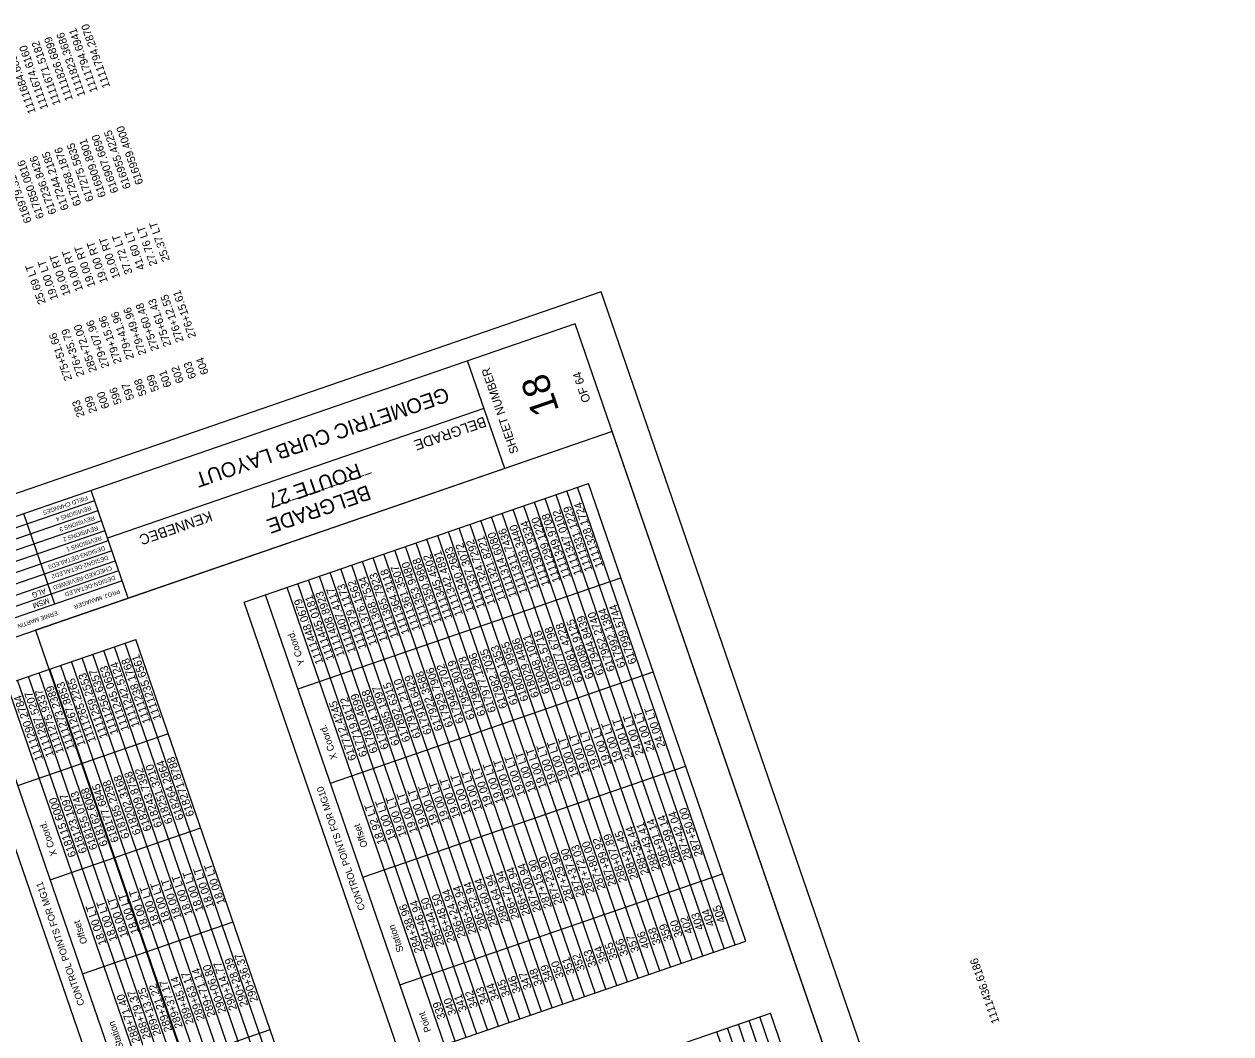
# Model space of a CAD drawing. Extents: x 1111039 to 1111836, y 617707 to 618808.
# Drawn here: x 1111305 to 1111836, y 618364 to 618808 of the extents above; entities that cross this region are included whole.
import ezdxf

# ---------------------------------------------------------------- set-up
doc = ezdxf.new("R2010")
doc.units = 0
for name, color, linetype in [('ANNOTATION', 7, 'Continuous'), ('BORDER', 7, 'Continuous'), ('BRIDGE_TITLE', 7, 'Continuous'), ('CLIPS', 7, 'Continuous'), ('H_V CONTROLS', 7, 'Continuous'), ('HIGHWAY_TITLE', 7, 'Continuous'), ('PLOT BOUNDARY', 7, 'Continuous')]:
    doc.layers.add(name, color=color, linetype=linetype)

msp = doc.modelspace()

# ---------------------------------------------------------------- linework, layer by layer
at = {"layer": 'BORDER'}
for p, q in [((1111547.51, 618675.96), (1111051.11, 618505.04)), ((1111807.98, 617919.56), (1111547.52, 618675.97)), ((1111516.51, 618612.41), (1111500.23, 618659.69)), ((1111507.41, 618638.84), (1111341.94, 618581.87)), ((1111563.79, 618628.69), (1111067.39, 618457.77)), ((1111351.05, 618555.44), (1111334.77, 618602.71))]:
    msp.add_line(p, q, dxfattribs=at)
for points in [[(1111336.27, 618598.31), (1111253.55, 618569.82)], [(1111337.78, 618593.9), (1111255.07, 618565.42)], [(1111339.3, 618589.5), (1111256.58, 618561.02)], [(1111318.87, 618552.9), (1111305.22, 618592.54)], [(1111340.82, 618585.09), (1111258.1, 618556.61)], [(1111342.33, 618580.69), (1111259.62, 618552.21)], [(1111343.85, 618576.28), (1111261.13, 618547.8)], [(1111262.65, 618543.4), (1111345.37, 618571.88)], [(1111346.88, 618567.47), (1111264.17, 618538.99)], [(1111348.4, 618563.07), (1111269.02, 618535.74)]]:
    msp.add_lwpolyline(points, dxfattribs=at)
at = {"layer": 'CLIPS'}
msp.add_lwpolyline([(1111807.98, 617919.56), (1111563.8, 618628.7), (1111310.4, 618541.44), (1111554.58, 617832.3)], close=True, dxfattribs=at)
at = {"layer": 'H_V CONTROLS'}
for p, q in [((1111402, 618553.73), (1111553.28, 618605.82)), ((1111617.74, 618403.27), (1111548.56, 618604.19)), ((1111622.47, 618404.89), (1111553.28, 618605.82)), ((1111603.56, 618398.38), (1111534.37, 618599.3)), ((1111608.28, 618400.01), (1111539.1, 618600.93)), ((1111613.01, 618401.64), (1111543.83, 618602.56)), ((1111589.37, 618393.5), (1111520.19, 618594.42)), ((1111594.1, 618395.13), (1111524.92, 618596.05)), ((1111598.83, 618396.75), (1111529.65, 618597.68)), ((1111575.19, 618388.61), (1111506.01, 618589.54)), ((1111579.92, 618390.24), (1111510.74, 618591.17)), ((1111584.65, 618391.87), (1111515.46, 618592.79)), ((1111556.28, 618382.1), (1111487.1, 618583.03)), ((1111561.01, 618383.73), (1111491.83, 618584.65)), ((1111565.74, 618385.36), (1111496.55, 618586.28)), ((1111570.46, 618386.99), (1111501.28, 618587.91)), ((1111542.1, 618377.22), (1111472.92, 618578.14)), ((1111546.83, 618378.85), (1111477.64, 618579.77)), ((1111551.55, 618380.48), (1111482.37, 618581.4)), ((1111527.92, 618372.34), (1111458.73, 618573.26)), ((1111532.64, 618373.96), (1111463.46, 618574.89)), ((1111537.37, 618375.59), (1111468.19, 618576.51)), ((1111513.73, 618367.45), (1111444.55, 618568.38)), ((1111518.46, 618369.08), (1111449.28, 618570)), ((1111523.19, 618370.71), (1111454, 618571.63)), ((1111494.82, 618360.94), (1111425.64, 618561.86)), ((1111425.7, 618515.61), (1111567.53, 618564.45)), ((1111499.55, 618362.57), (1111430.37, 618563.49)), ((1111504.28, 618364.2), (1111435.09, 618565.12)), ((1111509.01, 618365.83), (1111439.82, 618566.75)), ((1111480.64, 618356.06), (1111411.46, 618556.98)), ((1111490.09, 618359.31), (1111420.91, 618560.24)), ((1111471.18, 618352.8), (1111402, 618553.73)), ((1111278.86, 618511.33), (1111354.5, 618537.37)), ((1111418.96, 618334.82), (1111349.78, 618535.74)), ((1111423.69, 618336.45), (1111354.5, 618537.37)), ((1111423.69, 618336.45), (1111354.5, 618537.37)), ((1111404.78, 618329.94), (1111335.59, 618530.86)), ((1111409.51, 618331.56), (1111340.32, 618532.49)), ((1111414.23, 618333.19), (1111345.05, 618534.12)), ((1111390.59, 618325.05), (1111321.41, 618525.98)), ((1111395.32, 618326.68), (1111326.14, 618527.6)), ((1111400.05, 618328.31), (1111330.87, 618529.23)), ((1111371.68, 618318.54), (1111302.5, 618519.46)), ((1111376.41, 618320.17), (1111307.23, 618521.09)), ((1111381.14, 618321.8), (1111311.96, 618522.72)), ((1111385.87, 618323.43), (1111316.68, 618524.35)), ((1111439.94, 618474.25), (1111581.77, 618523.08)), ((1111357.5, 618313.66), (1111288.32, 618514.58)), ((1111366.96, 618316.91), (1111297.77, 618517.84)), ((1111348.05, 618310.4), (1111278.86, 618511.33)), ((1111302.56, 618473.21), (1111368.75, 618496)), ((1111454.19, 618432.88), (1111596.02, 618481.72)), ((1111316.81, 618431.85), (1111382.99, 618454.64)), ((1111470.47, 618385.61), (1111612.29, 618434.44)), ((1111331.05, 618390.48), (1111397.24, 618413.27)), ((1111471.18, 618352.8), (1111622.47, 618404.89)), ((1111557.73, 618347.19), (1111633.37, 618373.23)), ((1111697.82, 618170.68), (1111628.64, 618371.61)), ((1111702.55, 618172.31), (1111633.37, 618373.23)), ((1111702.55, 618172.31), (1111633.37, 618373.23)), ((1111347.33, 618343.21), (1111413.51, 618366)), ((1111683.64, 618165.8), (1111614.46, 618366.72)), ((1111688.37, 618167.43), (1111619.19, 618368.35)), ((1111693.1, 618169.06), (1111623.91, 618369.98)), ((1111678.91, 618164.17), (1111609.73, 618365.09))]:
    msp.add_line(p, q, dxfattribs=at)
at = {"layer": 'PLOT BOUNDARY'}
msp.add_lwpolyline([(1111835.61, 617886.27), (1111558.88, 618689.96), (1111038.85, 618510.9), (1111315.58, 617707.21)], close=True, dxfattribs=at)

# ---------------------------------------------------------------- texts
at = {"layer": 'ANNOTATION'}
for s, height, p in [('1111794.6941', 3.45, (1111337.74, 618778.28)), ('1111794.2870', 3.45, (1111343.19, 618780.16)), ('1111826.6899', 3.45, (1111326.85, 618774.53)), ('1111823.3686', 3.45, (1111332.29, 618776.4)), ('1111684.6898', 3.45, (1111310.5, 618768.9)), ('1111674.6160', 3.45, (1111315.95, 618770.78)), ('1111671.5182', 3.45, (1111321.4, 618772.65)), ('616907.6690', 3.45, (1111346.88, 618734.04)), ('616955.4225', 3.45, (1111352.33, 618735.91)), ('616959.4000', 3.45, (1111357.78, 618737.79)), ('617268.1876', 3.45, (1111330.54, 618728.41)), ('617275.5635', 3.45, (1111335.99, 618730.28)), ('616909.8901', 3.45, (1111341.43, 618732.16)), ('617850.0816', 3.45, (1111314.2, 618722.78)), ('617236.8426', 3.45, (1111319.64, 618724.66)), ('617244.2185', 3.45, (1111325.09, 618726.53)), ('616979.3193', 3.45, (1111308.75, 618720.9)), ('41.60 LT', 3.45, (1111358.53, 618700.22)), ('27.76 LT', 3.45, (1111363.97, 618702.1)), ('25.37 LT', 3.45, (1111369.42, 618703.97)), ('19.00 RT', 3.45, (1111342.18, 618694.6)), ('19.00 RT', 3.45, (1111347.63, 618696.47)), ('37.72 LT', 3.45, (1111353.08, 618698.35)), ('19.00 RT', 3.45, (1111325.84, 618688.97)), ('19.00 RT', 3.45, (1111331.29, 618690.84)), ('19.00 RT', 3.45, (1111336.73, 618692.72)), ('25.69 LT', 3.45, (1111314.94, 618685.22)), ('19.00 LT', 3.45, (1111320.39, 618687.09)), ('276+15.61', 3.45, (1111380.99, 618670.37)), ('275+60.48', 3.45, (1111364.65, 618664.74)), ('275+61.43', 3.45, (1111370.1, 618666.62)), ('276+12.55', 3.45, (1111375.54, 618668.5)), ('279+15.96', 3.45, (1111348.31, 618659.12)), ('279+41.96', 3.45, (1111353.75, 618660.99)), ('279+49.96', 3.45, (1111359.2, 618662.87)), ('276+35.79', 3.45, (1111331.96, 618653.49)), ('285+72.00', 3.45, (1111337.41, 618655.36)), ('279+07.96', 3.45, (1111342.86, 618657.24)), ('275+51.66', 3.45, (1111326.51, 618651.61)), ('602', 3.45, (1111375.62, 618650.58)), ('603', 3.45, (1111381.07, 618652.46)), ('604', 3.45, (1111386.51, 618654.33)), ('599', 3.45, (1111364.72, 618646.83)), ('601', 3.45, (1111370.17, 618648.71)), ('596', 3.45, (1111348.38, 618641.2)), ('597', 3.45, (1111353.83, 618643.08)), ('598', 3.45, (1111359.28, 618644.95)), ('283', 3.45, (1111332.04, 618635.58)), ('299', 3.45, (1111337.48, 618637.45)), ('600', 3.45, (1111342.93, 618639.33)), ('1111347.0102', 3.5156, (1111550.47, 618566.28)), ('1111331.1229', 3.5156, (1111555.15, 618567.9)), ('1111328.1724', 3.5156, (1111559.91, 618569.53)), ('1111301.9334', 3.5156, (1111536.35, 618561.42)), ('1111299.1220', 3.5156, (1111541.11, 618563.06)), ('1111349.9708', 3.5156, (1111545.68, 618564.63)), ('1111321.8221', 3.5156, (1111517.2, 618554.83)), ('1111314.6080', 3.5156, (1111521.95, 618556.46)), ('1111311.7436', 3.5156, (1111526.65, 618558.08)), ('1111303.3440', 3.5156, (1111531.5, 618559.75)), ('1111340.2683', 3.5156, (1111503.15, 618549.99)), ('1111337.3072', 3.5156, (1111507.87, 618551.62)), ('1111324.7292', 3.5156, (1111512.48, 618553.2)), ('1111350.9868', 3.5156, (1111488.92, 618545.09)), ('1111345.4502', 3.5156, (1111493.64, 618546.71)), ('1111342.4891', 3.5156, (1111498.21, 618548.29)), ('1111364.3118', 3.5156, (1111474.76, 618540.22)), ('1111361.3507', 3.5156, (1111479.41, 618541.81)), ('1111353.9480', 3.5156, (1111484.12, 618543.44)), ('1111379.1173', 3.5156, (1111455.83, 618533.7)), ('1111376.1562', 3.5156, (1111460.53, 618535.31)), ('1111368.7534', 3.5156, (1111465.25, 618536.94)), ('1111365.7923', 3.5156, (1111469.97, 618538.56)), ('1111445.0181', 3.5156, (1111441.65, 618528.81)), ('1111408.8923', 3.5156, (1111446.28, 618530.41)), ('1111407.4117', 3.5156, (1111451.11, 618532.07)), ('1111448.0679', 3.5156, (1111436.86, 618527.16)), ('617999.5744', 3.5156, (1111574.51, 618527.15)), ('618088.9125', 3.5156, (1111555.71, 618520.67)), ('617944.8439', 3.5156, (1111560.27, 618522.24)), ('617952.2740', 3.5156, (1111565.07, 618523.9)), ('617992.1384', 3.5156, (1111569.75, 618525.51)), ('618055.5718', 3.5156, (1111541.25, 618515.69)), ('618077.6798', 3.5156, (1111546.1, 618517.36)), ('618081.4228', 3.5156, (1111550.95, 618519.03)), ('618021.9955', 3.5156, (1111527.07, 618510.81)), ('618029.4486', 3.5156, (1111531.79, 618512.44)), ('618048.1021', 3.5156, (1111536.55, 618514.07)), ('1111235.6561', 3.5156, (1111365.59, 618502.63)), ('617977.1296', 3.5156, (1111512.8, 618505.9)), ('617982.7035', 3.5156, (1111517.75, 618507.6)), ('617990.1353', 3.5156, (1111522.47, 618509.23)), ('1111245.0653', 3.5156, (1111351.55, 618497.79)), ('1111242.5124', 3.5156, (1111356.19, 618499.39)), ('1111238.1768', 3.5156, (1111361.02, 618501.05)), ('617929.7906', 3.5156, (1111494, 618499.43)), ('617948.3702', 3.5156, (1111498.72, 618501.05)), ('617955.8019', 3.5156, (1111503.51, 618502.7)), ('617969.6978', 3.5156, (1111508.23, 618504.33)), ('1111265.2265', 3.45, (1111337, 618492.78)), ('1111259.2553', 3.5156, (1111342.15, 618494.55)), ('1111256.6357', 3.5156, (1111346.83, 618496.16)), ('617911.2110', 3.5156, (1111479.84, 618494.55)), ('617918.6429', 3.5156, (1111484.56, 618496.18)), ('617922.3588', 3.5156, (1111489.36, 618497.83)), ('1111275.9337', 3.45, (1111322.89, 618487.92)), ('1111273.2389', 3.45, (1111327.63, 618489.55)), ('1111267.8853', 3.45, (1111332.35, 618491.18)), ('617814.1858', 3.5156, (1111465.71, 618489.68)), ('617885.1997', 3.5156, (1111470.42, 618491.31)), ('617892.6315', 3.5156, (1111475.13, 618492.93)), ('1111290.2784', 3.5156, (1111313.74, 618484.77)), ('1111287.5207', 3.5156, (1111318.48, 618486.4)), ('617712.4245', 3.5156, (1111451.45, 618484.77)), ('617719.8172', 3.5156, (1111456.25, 618486.43)), ('617810.4699', 3.5156, (1111460.87, 618488.02)), ('24.00 LT', 3.516, (1111577.71, 618487.17)), ('24.00 LT', 3.516, (1111582.39, 618488.78)), ('24.00 LT', 3.516, (1111587.15, 618490.42)), ('19.00 LT', 3.516, (1111563.59, 618482.31)), ('19.00 LT', 3.516, (1111568.22, 618483.9)), ('24.00 LT', 3.516, (1111573.05, 618485.57)), ('19.00 LT', 3.516, (1111549.17, 618477.35)), ('19.00 LT', 3.516, (1111553.89, 618478.97)), ('19.00 LT', 3.516, (1111558.59, 618480.59)), ('19.00 LT', 3.516, (1111535.04, 618472.48)), ('19.00 LT', 3.516, (1111539.72, 618474.09)), ('19.00 LT', 3.516, (1111544.34, 618475.68)), ('618251.3210', 3.5156, (1111370.79, 618457)), ('618264.2864', 3.5156, (1111375.62, 618458.66)), ('618271.8788', 3.5156, (1111380.19, 618460.24)), ('19.00 LT', 3.516, (1111516.16, 618465.98)), ('19.00 LT', 3.516, (1111520.78, 618467.57)), ('19.00 LT', 3.516, (1111525.62, 618469.23)), ('19.00 LT', 3.516, (1111530.34, 618470.86)), ('618202.3168', 3.5156, (1111356.74, 618452.16)), ('618209.8758', 3.5156, (1111361.43, 618453.78)), ('618243.7392', 3.5156, (1111366.14, 618455.4)), ('19.00 LT', 3.516, (1111501.95, 618461.08)), ('19.00 LT', 3.516, (1111506.67, 618462.71)), ('19.00 LT', 3.516, (1111511.37, 618464.33)), ('618162.6068', 3.45, (1111342.21, 618447.16)), ('618177.6845', 3.45, (1111347.08, 618448.84)), ('618185.2298', 3.45, (1111351.78, 618450.45)), ('19.00 LT', 3.516, (1111487.77, 618456.2)), ('19.00 LT', 3.516, (1111492.49, 618457.83)), ('19.00 LT', 3.516, (1111497.11, 618459.42)), ('618115.6000', 3.5156, (1111328.34, 618442.38)), ('618123.1097', 3.5156, (1111333.07, 618444.01)), ('618155.0743', 3.45, (1111337.66, 618445.59)), ('19.00 LT', 3.516, (1111473.52, 618451.29)), ('19.00 LT', 3.516, (1111478.35, 618452.96)), ('19.00 LT', 3.516, (1111483.07, 618454.58)), ('18.92 LT', 3.516, (1111464.1, 618448.05)), ('19.00 LT', 3.516, (1111468.89, 618449.7)), ('287+42.04', 3.516, (1111598.82, 618441.09)), ('287+50.00', 3.516, (1111603.57, 618442.73)), ('288+43.41', 3.516, (1111584.77, 618436.25)), ('286+91.14', 3.516, (1111589.34, 618437.82)), ('286+99.14', 3.516, (1111594.14, 618439.48)), ('287+99.92', 3.516, (1111565.62, 618429.66)), ('288+07.89', 3.516, (1111570.32, 618431.27)), ('288+31.45', 3.516, (1111575.3, 618432.55)), ('288+35.44', 3.516, (1111580.02, 618434.61)), ('287+37.90', 3.516, (1111551.53, 618424.81)), ('287+72.03', 3.516, (1111556.14, 618426.39)), ('287+80.00', 3.516, (1111560.86, 618428.02)), ('287+15.90', 3.516, (1111537.3, 618419.91)), ('287+23.90', 3.516, (1111541.87, 618421.48)), ('287+29.90', 3.516, (1111546.81, 618423.18)), ('18.00 LT', 3.516, (1111384.26, 618418.43)), ('18.00 LT', 3.516, (1111388.92, 618420.03)), ('18.00 LT', 3.516, (1111393.66, 618421.66)), ('286+72.94', 3.516, (1111523.07, 618415.01)), ('286+92.94', 3.516, (1111527.79, 618416.63)), ('287+00.94', 3.516, (1111532.58, 618418.28)), ('18.00 LT', 3.516, (1111370.05, 618413.53)), ('18.00 LT', 3.516, (1111374.73, 618415.15)), ('18.00 LT', 3.516, (1111379.46, 618416.78)), ('286+32.94', 3.516, (1111504.19, 618408.51)), ('286+52.94', 3.516, (1111508.91, 618410.13)), ('286+60.94', 3.516, (1111513.63, 618411.76)), ('286+64.94', 3.516, (1111518.43, 618413.41)), ('18.00 LT', 3.516, (1111355.9, 618408.66)), ('18.00 LT', 3.516, (1111360.63, 618410.29)), ('18.00 LT', 3.516, (1111365.35, 618411.92)), ('285+48.50', 3.516, (1111494.91, 618404.87)), ('286+24.94', 3.516, (1111499.49, 618406.89)), ('18.00 LT', 3.516, (1111341.64, 618403.75)), ('18.00 LT', 3.516, (1111346.37, 618405.38)), ('18.00 LT', 3.516, (1111351.17, 618407.03)), ('284+38.96', 3.516, (1111480.52, 618400.35)), ('284+46.94', 3.516, (1111485.32, 618402.01)), ('285+44.50', 3.516, (1111490.08, 618403.21)), ('404', 3.516, (1111608.85, 618411.95)), ('405', 3.516, (1111613.61, 618413.59)), ('360', 3.516, (1111594.81, 618407.12)), ('402', 3.516, (1111599.37, 618408.69)), ('403', 3.516, (1111604.17, 618410.34)), ('406', 3.516, (1111580.35, 618402.14)), ('358', 3.516, (1111585.2, 618403.81)), ('359', 3.516, (1111590.05, 618405.48)), ('354', 3.516, (1111561.57, 618395.67)), ('355', 3.516, (1111566.17, 618397.26)), ('356', 3.516, (1111570.89, 618398.88)), ('357', 3.516, (1111575.65, 618400.52)), ('290+36.37', 3.516, (1111408.27, 618378.69)), ('351', 3.516, (1111547.33, 618390.77)), ('352', 3.516, (1111551.9, 618392.34)), ('353', 3.516, (1111556.85, 618394.05)), ('289+71.14', 3.516, (1111389.5, 618372.23)), ('290+06.80', 3.516, (1111394.22, 618373.85)), ('290+14.77', 3.516, (1111399, 618375.06)), ('290+28.39', 3.516, (1111403.83, 618376.73)), ('348', 3.516, (1111533.1, 618385.87)), ('349', 3.516, (1111537.82, 618387.49)), ('350', 3.516, (1111542.61, 618389.14)), ('1111436.6186', 3.5156, (1111734, 618369.32)), ('289+37.17', 3.45, (1111375.1, 618367.27)), ('289+45.14', 3.45, (1111379.98, 618368.95)), ('289+63.17', 3.516, (1111384.82, 618370.62)), ('345', 3.516, (1111518.94, 618380.99)), ('346', 3.516, (1111523.66, 618382.62)), ('347', 3.516, (1111528.46, 618384.27)), ('288+71.40', 3.516, (1111356.41, 618360.83)), ('288+79.37', 3.516, (1111361.15, 618362.47)), ('289+13.25', 3.45, (1111365.62, 618364)), ('289+21.22', 3.45, (1111370.45, 618365.67)), ('341', 3.516, (1111499.97, 618374.46)), ('342', 3.516, (1111504.81, 618376.13)), ('343', 3.516, (1111509.53, 618377.75)), ('344', 3.516, (1111514.23, 618379.37)), ('339', 3.516, (1111490.55, 618371.22)), ('340', 3.516, (1111495.35, 618372.87))]:
    msp.add_text(s, height=height, rotation=109, dxfattribs=at).set_placement(p)
at = {"layer": 'BORDER'}
for s, height, rotation, p in [('SHEET NUMBER', 3.7264, 109, (1111522.68, 618619.64)), ('18', 12.097, 109, (1111540.59, 618638)), ('OF 64', 3.726, 109, (1111554.33, 618642.18)), ('GEOMETRIC CURB LAYOUT', 6.5214, 199, (1111490.75, 618648.3)), ('FIELD CHANGES', 1.8637, 199, (1111332.94, 618600.51)), ('REVISIONS 4', 1.8637, 199, (1111334.46, 618596.11)), ('REVISIONS 3', 1.8637, 199, (1111335.98, 618591.7)), ('REVISIONS 2', 1.8637, 199, (1111337.49, 618587.3)), ('DESIGN3-DETAILED3', 1.8637, 199, (1111340.53, 618578.49)), ('REVISIONS 1', 1.8637, 199, (1111339.01, 618582.89)), ('DESIGN2-DETAILED2', 1.8637, 199, (1111341.98, 618574.26)), ('CHECKED-REVIEWED', 1.8637, 199, (1111343.56, 618569.68)), ('DESIGN-DETAILED', 1.8637, 199, (1111345.02, 618565.45)), ('ALG', 2.423, 199, (1111314.5, 618559.86)), ('PROJ. MANAGER', 1.8637, 199, (1111347.1, 618559.39)), ('MSM', 2.423, 199, (1111315.95, 618555.64)), ('ERNIE MARTIN', 1.8637, 199, (1111319.67, 618549.94))]:
    msp.add_text(s, height=height, rotation=rotation, dxfattribs=at).set_placement(p)
at = {"layer": 'BRIDGE_TITLE'}
for s, height, p in [('BELGRADE', 4.536, (1111507.46, 618635.31)), ('_____________', 4.5358, (1111458.34, 618609.53)), ('KENNEBEC', 4.536, (1111387.07, 618593.86))]:
    msp.add_text(s, height=height, rotation=199, dxfattribs=at).set_placement(p)
at = {"layer": 'H_V CONTROLS'}
for s, p in [('Y Coord.', (1111428.78, 618526.63)), ('X Coord.', (1111443.02, 618485.26)), ('CONTROL POINTS FOR MG10', (1111455.28, 618418.95)), ('X Coord.', (1111319.89, 618442.86)), ('Offset', (1111456.35, 618446.56)), ('CONTROL POINTS FOR MG11', (1111331.96, 618377.08)), ('Offset', (1111333.21, 618404.16)), ('Station', (1111472.17, 618400.62)), ('Point', (1111484.28, 618365.44)), ('Station', (1111349.03, 618358.22))]:
    msp.add_text(s, height=3, rotation=109, dxfattribs=at).set_placement(p)
at = {"layer": 'HIGHWAY_TITLE'}
for s, p in [('ROUTE 27', (1111452.05, 618614.85)), ('BELGRADE', (1111456.28, 618605.27))]:
    msp.add_text(s, height=6.521, rotation=199, dxfattribs=at).set_placement(p)

doc.saveas('drawing.dxf')
